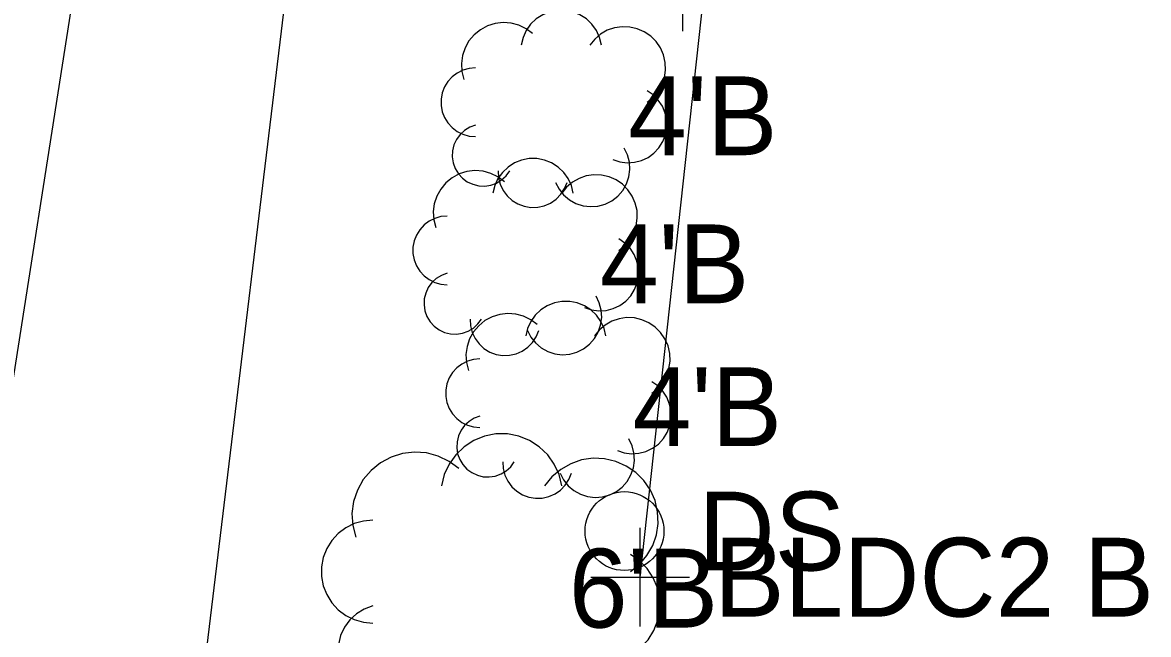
# Model space of a CAD drawing. Extents: x 1363693 to 1365209, y 422201 to 424153.
# Drawn here: x 1364320.23 to 1364343.06, y 423350.74 to 423363.16 of the extents above; entities that cross this region are included whole.
import ezdxf

# ---------------------------------------------------------------- set-up
doc = ezdxf.new("R2010")
doc.units = 0
for name, color, linetype in [('BD_X_Building', 7, 'Continuous'), ('DR_X_Cells', 7, 'Continuous'), ('DR_X_Text', 7, 'Continuous'), ('PV_X_Driveway', 7, 'Continuous'), ('SV_X_Original_Ground', 7, 'Continuous'), ('SV_X_Shot_Marker', 7, 'Continuous'), ('VG_X_Cells', 7, 'Continuous'), ('VG_X_Text', 7, 'Continuous')]:
    doc.layers.add(name, color=color, linetype=linetype)

msp = doc.modelspace()

# ---------------------------------------------------------------- linework, layer by layer
at = {"layer": 'BD_X_Building'}
msp.add_line((1364332.753, 423351.902), (1364336.998, 423390.69), dxfattribs=at)
at = {"layer": 'DR_X_Cells'}
msp.add_circle((1364332.436, 423352.838), 0.8, dxfattribs=at)
at = {"layer": 'PV_X_Driveway'}
for points in [[(1364331.792, 423345.218), (1364318.569, 423346.527), (1364322.532, 423371.799)], [(1364332.146, 423348.047), (1364323.796, 423349.002), (1364325.909, 423366.51), (1364326.847, 423366.42)]]:
    msp.add_lwpolyline(points, dxfattribs=at)
at = {"layer": 'SV_X_Original_Ground'}
msp.add_line((1364333.622, 423362.98), (1364333.622, 423364.98), dxfattribs=at)
at = {"layer": 'SV_X_Shot_Marker'}
for p, q in [((1364332.753, 423350.902), (1364332.753, 423352.902)), ((1364331.753, 423351.902), (1364333.753, 423351.902))]:
    msp.add_line(p, q, dxfattribs=at)
at = {"layer": 'VG_X_Cells'}
for points in [[(1364331.968, 423362.699), (1364331.931, 423362.851), (1364331.866, 423362.993), (1364331.776, 423363.12), (1364331.663, 423363.228), (1364331.531, 423363.313), (1364331.386, 423363.371), (1364331.233, 423363.4), (1364331.077, 423363.4), (1364330.923, 423363.371), (1364330.779, 423363.313), (1364330.647, 423363.228), (1364330.534, 423363.12), (1364330.444, 423362.993), (1364330.379, 423362.851), (1364330.342, 423362.699)], [(1364330.574, 423362.931), (1364330.444, 423363.029), (1364330.297, 423363.101), (1364330.14, 423363.143), (1364329.977, 423363.156), (1364329.815, 423363.137), (1364329.659, 423363.088), (1364329.515, 423363.011), (1364329.389, 423362.908), (1364329.284, 423362.783), (1364329.204, 423362.64), (1364329.153, 423362.485), (1364329.131, 423362.324), (1364329.141, 423362.161), (1364329.181, 423362.002)], [(1364332.897, 423361.538), (1364333.017, 423361.636), (1364333.118, 423361.755), (1364333.195, 423361.89), (1364333.246, 423362.037), (1364333.268, 423362.191), (1364333.262, 423362.346), (1364333.227, 423362.498), (1364333.164, 423362.641), (1364333.077, 423362.769), (1364332.967, 423362.879), (1364332.838, 423362.967), (1364332.696, 423363.029), (1364332.544, 423363.064), (1364332.388, 423363.071), (1364332.234, 423363.048), (1364332.087, 423362.998), (1364331.952, 423362.921), (1364331.833, 423362.82), (1364331.735, 423362.699)], [(1364329.413, 423362.235), (1364329.285, 423362.223), (1364329.162, 423362.188), (1364329.047, 423362.13), (1364328.944, 423362.053), (1364328.857, 423361.958), (1364328.79, 423361.849), (1364328.743, 423361.729), (1364328.72, 423361.602), (1364328.72, 423361.474), (1364328.743, 423361.347), (1364328.79, 423361.227), (1364328.857, 423361.118), (1364328.944, 423361.023), (1364329.047, 423360.946), (1364329.162, 423360.888), (1364329.285, 423360.853), (1364329.413, 423360.841)], [(1364332.2, 423360.377), (1364332.341, 423360.33), (1364332.488, 423360.311), (1364332.636, 423360.32), (1364332.779, 423360.357), (1364332.913, 423360.42), (1364333.033, 423360.507), (1364333.134, 423360.616), (1364333.212, 423360.741), (1364333.266, 423360.88), (1364333.292, 423361.026), (1364333.29, 423361.174), (1364333.26, 423361.319), (1364333.204, 423361.456), (1364333.122, 423361.58), (1364333.018, 423361.686), (1364332.897, 423361.77)], [(1364329.413, 423361.074), (1364329.298, 423361.031), (1364329.193, 423360.967), (1364329.102, 423360.884), (1364329.03, 423360.785), (1364328.978, 423360.673), (1364328.949, 423360.554), (1364328.944, 423360.431), (1364328.962, 423360.31), (1364329.004, 423360.194), (1364329.068, 423360.089), (1364329.151, 423359.998), (1364329.25, 423359.926), (1364329.362, 423359.874), (1364329.481, 423359.844), (1364329.604, 423359.839), (1364329.725, 423359.857), (1364329.841, 423359.899), (1364329.946, 423359.963), (1364330.037, 423360.046), (1364330.11, 423360.145)], [(1364331.039, 423359.913), (1364331.109, 423359.778), (1364331.203, 423359.659), (1364331.319, 423359.561), (1364331.452, 423359.487), (1364331.596, 423359.44), (1364331.747, 423359.421), (1364331.898, 423359.433), (1364332.044, 423359.473), (1364332.18, 423359.541), (1364332.3, 423359.634), (1364332.4, 423359.748), (1364332.476, 423359.88), (1364332.525, 423360.023), (1364332.546, 423360.174), (1364332.536, 423360.325), (1364332.498, 423360.472), (1364332.432, 423360.609)], [(1364331.396, 423359.694), (1364331.359, 423359.846), (1364331.294, 423359.988), (1364331.204, 423360.115), (1364331.091, 423360.223), (1364330.959, 423360.308), (1364330.814, 423360.366), (1364330.661, 423360.395), (1364330.505, 423360.395), (1364330.351, 423360.366), (1364330.207, 423360.308), (1364330.075, 423360.223), (1364329.962, 423360.115), (1364329.872, 423359.988), (1364329.807, 423359.846), (1364329.77, 423359.694)], [(1364330.002, 423359.926), (1364329.872, 423360.024), (1364329.725, 423360.096), (1364329.568, 423360.138), (1364329.405, 423360.151), (1364329.243, 423360.132), (1364329.087, 423360.083), (1364328.943, 423360.006), (1364328.817, 423359.903), (1364328.712, 423359.778), (1364328.632, 423359.635), (1364328.581, 423359.48), (1364328.559, 423359.319), (1364328.569, 423359.156), (1364328.609, 423358.997)], [(1364329.878, 423360.145), (1364329.885, 423360.008), (1364329.919, 423359.875), (1364329.978, 423359.751), (1364330.059, 423359.641), (1364330.16, 423359.548), (1364330.276, 423359.476), (1364330.405, 423359.428), (1364330.54, 423359.406), (1364330.677, 423359.409), (1364330.811, 423359.439), (1364330.936, 423359.494), (1364331.049, 423359.573), (1364331.144, 423359.671), (1364331.219, 423359.786), (1364331.271, 423359.913)], [(1364332.325, 423358.533), (1364332.445, 423358.631), (1364332.546, 423358.75), (1364332.623, 423358.885), (1364332.674, 423359.032), (1364332.696, 423359.186), (1364332.69, 423359.341), (1364332.655, 423359.493), (1364332.592, 423359.636), (1364332.505, 423359.764), (1364332.395, 423359.874), (1364332.266, 423359.962), (1364332.124, 423360.024), (1364331.972, 423360.059), (1364331.816, 423360.066), (1364331.662, 423360.043), (1364331.515, 423359.993), (1364331.38, 423359.916), (1364331.261, 423359.815), (1364331.163, 423359.694)], [(1364328.841, 423359.23), (1364328.713, 423359.218), (1364328.59, 423359.183), (1364328.475, 423359.125), (1364328.372, 423359.048), (1364328.285, 423358.953), (1364328.218, 423358.844), (1364328.171, 423358.724), (1364328.148, 423358.597), (1364328.148, 423358.469), (1364328.171, 423358.342), (1364328.218, 423358.222), (1364328.285, 423358.113), (1364328.372, 423358.018), (1364328.475, 423357.941), (1364328.59, 423357.883), (1364328.713, 423357.848), (1364328.841, 423357.836)], [(1364331.628, 423357.372), (1364331.769, 423357.325), (1364331.916, 423357.306), (1364332.064, 423357.315), (1364332.207, 423357.352), (1364332.341, 423357.415), (1364332.461, 423357.502), (1364332.562, 423357.611), (1364332.64, 423357.736), (1364332.694, 423357.875), (1364332.72, 423358.021), (1364332.718, 423358.169), (1364332.688, 423358.314), (1364332.632, 423358.451), (1364332.55, 423358.575), (1364332.446, 423358.681), (1364332.325, 423358.765)], [(1364328.841, 423358.069), (1364328.726, 423358.026), (1364328.621, 423357.962), (1364328.53, 423357.879), (1364328.458, 423357.78), (1364328.406, 423357.668), (1364328.377, 423357.549), (1364328.372, 423357.426), (1364328.39, 423357.305), (1364328.432, 423357.189), (1364328.496, 423357.084), (1364328.579, 423356.993), (1364328.678, 423356.921), (1364328.79, 423356.869), (1364328.909, 423356.839), (1364329.032, 423356.834), (1364329.153, 423356.852), (1364329.269, 423356.894), (1364329.374, 423356.958), (1364329.465, 423357.041), (1364329.538, 423357.14)], [(1364332.06, 423356.796), (1364332.023, 423356.948), (1364331.958, 423357.09), (1364331.868, 423357.217), (1364331.755, 423357.325), (1364331.623, 423357.41), (1364331.478, 423357.468), (1364331.325, 423357.497), (1364331.169, 423357.497), (1364331.015, 423357.468), (1364330.871, 423357.41), (1364330.739, 423357.325), (1364330.626, 423357.217), (1364330.536, 423357.09), (1364330.471, 423356.948), (1364330.434, 423356.796)], [(1364330.467, 423356.908), (1364330.537, 423356.773), (1364330.631, 423356.654), (1364330.747, 423356.556), (1364330.88, 423356.482), (1364331.024, 423356.435), (1364331.175, 423356.416), (1364331.326, 423356.428), (1364331.472, 423356.468), (1364331.608, 423356.536), (1364331.728, 423356.629), (1364331.828, 423356.743), (1364331.904, 423356.875), (1364331.953, 423357.018), (1364331.974, 423357.169), (1364331.964, 423357.32), (1364331.926, 423357.467), (1364331.86, 423357.604)], [(1364330.666, 423357.028), (1364330.536, 423357.126), (1364330.389, 423357.198), (1364330.232, 423357.24), (1364330.069, 423357.253), (1364329.907, 423357.234), (1364329.751, 423357.185), (1364329.607, 423357.108), (1364329.481, 423357.005), (1364329.376, 423356.88), (1364329.296, 423356.737), (1364329.245, 423356.582), (1364329.223, 423356.421), (1364329.233, 423356.258), (1364329.273, 423356.099)], [(1364329.306, 423357.14), (1364329.313, 423357.003), (1364329.347, 423356.87), (1364329.406, 423356.746), (1364329.487, 423356.636), (1364329.588, 423356.543), (1364329.704, 423356.471), (1364329.833, 423356.423), (1364329.968, 423356.401), (1364330.105, 423356.404), (1364330.239, 423356.434), (1364330.364, 423356.489), (1364330.477, 423356.568), (1364330.572, 423356.666), (1364330.647, 423356.781), (1364330.699, 423356.908)], [(1364332.989, 423355.635), (1364333.109, 423355.733), (1364333.21, 423355.852), (1364333.287, 423355.987), (1364333.338, 423356.134), (1364333.36, 423356.288), (1364333.354, 423356.443), (1364333.319, 423356.595), (1364333.256, 423356.738), (1364333.169, 423356.866), (1364333.059, 423356.976), (1364332.93, 423357.064), (1364332.788, 423357.126), (1364332.636, 423357.161), (1364332.48, 423357.168), (1364332.326, 423357.145), (1364332.179, 423357.095), (1364332.044, 423357.018), (1364331.925, 423356.917), (1364331.827, 423356.796)], [(1364329.505, 423356.332), (1364329.377, 423356.32), (1364329.254, 423356.285), (1364329.139, 423356.227), (1364329.036, 423356.15), (1364328.949, 423356.055), (1364328.882, 423355.946), (1364328.835, 423355.826), (1364328.812, 423355.699), (1364328.812, 423355.571), (1364328.835, 423355.444), (1364328.882, 423355.324), (1364328.949, 423355.215), (1364329.036, 423355.12), (1364329.139, 423355.043), (1364329.254, 423354.985), (1364329.377, 423354.95), (1364329.505, 423354.938)], [(1364332.292, 423354.474), (1364332.433, 423354.427), (1364332.58, 423354.408), (1364332.728, 423354.417), (1364332.871, 423354.454), (1364333.005, 423354.517), (1364333.125, 423354.604), (1364333.226, 423354.713), (1364333.304, 423354.838), (1364333.358, 423354.977), (1364333.384, 423355.123), (1364333.382, 423355.271), (1364333.352, 423355.416), (1364333.296, 423355.553), (1364333.214, 423355.677), (1364333.11, 423355.783), (1364332.989, 423355.867)], [(1364329.505, 423355.171), (1364329.39, 423355.128), (1364329.285, 423355.064), (1364329.194, 423354.981), (1364329.122, 423354.882), (1364329.07, 423354.77), (1364329.041, 423354.651), (1364329.036, 423354.528), (1364329.054, 423354.407), (1364329.096, 423354.291), (1364329.16, 423354.186), (1364329.243, 423354.095), (1364329.342, 423354.023), (1364329.454, 423353.971), (1364329.573, 423353.941), (1364329.696, 423353.936), (1364329.817, 423353.954), (1364329.933, 423353.996), (1364330.038, 423354.06), (1364330.129, 423354.143), (1364330.202, 423354.242)], [(1364331.167, 423353.757), (1364331.111, 423353.984), (1364331.014, 423354.197), (1364330.879, 423354.388), (1364330.709, 423354.55), (1364330.512, 423354.677), (1364330.295, 423354.764), (1364330.065, 423354.808), (1364329.83, 423354.808), (1364329.6, 423354.764), (1364329.383, 423354.677), (1364329.186, 423354.55), (1364329.016, 423354.388), (1364328.88, 423354.197), (1364328.783, 423353.984), (1364328.728, 423353.757)], [(1364331.131, 423354.01), (1364331.201, 423353.875), (1364331.295, 423353.756), (1364331.411, 423353.658), (1364331.544, 423353.584), (1364331.688, 423353.537), (1364331.839, 423353.518), (1364331.99, 423353.53), (1364332.136, 423353.57), (1364332.272, 423353.638), (1364332.392, 423353.731), (1364332.492, 423353.845), (1364332.568, 423353.977), (1364332.617, 423354.12), (1364332.638, 423354.271), (1364332.628, 423354.422), (1364332.59, 423354.569), (1364332.524, 423354.706)], [(1364329.077, 423354.105), (1364328.881, 423354.252), (1364328.661, 423354.359), (1364328.424, 423354.423), (1364328.18, 423354.441), (1364327.937, 423354.413), (1364327.703, 423354.34), (1364327.488, 423354.224), (1364327.298, 423354.07), (1364327.14, 423353.882), (1364327.021, 423353.669), (1364326.944, 423353.436), (1364326.912, 423353.193), (1364326.927, 423352.949), (1364326.987, 423352.712)], [(1364332.56, 423352.015), (1364332.741, 423352.162), (1364332.892, 423352.34), (1364333.008, 423352.543), (1364333.084, 423352.764), (1364333.117, 423352.994), (1364333.108, 423353.228), (1364333.055, 423353.455), (1364332.962, 423353.669), (1364332.83, 423353.862), (1364332.665, 423354.027), (1364332.472, 423354.158), (1364332.258, 423354.252), (1364332.031, 423354.305), (1364331.798, 423354.314), (1364331.567, 423354.28), (1364331.346, 423354.204), (1364331.143, 423354.089), (1364330.965, 423353.938), (1364330.818, 423353.757)], [(1364329.97, 423354.242), (1364329.977, 423354.105), (1364330.011, 423353.972), (1364330.07, 423353.848), (1364330.151, 423353.738), (1364330.252, 423353.645), (1364330.368, 423353.573), (1364330.497, 423353.525), (1364330.632, 423353.503), (1364330.769, 423353.506), (1364330.903, 423353.536), (1364331.028, 423353.591), (1364331.141, 423353.67), (1364331.236, 423353.768), (1364331.311, 423353.883), (1364331.363, 423354.01)], [(1364327.335, 423353.06), (1364327.143, 423353.042), (1364326.958, 423352.989), (1364326.785, 423352.903), (1364326.631, 423352.787), (1364326.501, 423352.645), (1364326.4, 423352.481), (1364326.33, 423352.301), (1364326.295, 423352.111), (1364326.295, 423351.919), (1364326.33, 423351.729), (1364326.4, 423351.549), (1364326.501, 423351.385), (1364326.631, 423351.243), (1364326.785, 423351.127), (1364326.958, 423351.041), (1364327.143, 423350.988), (1364327.335, 423350.97)], [(1364331.515, 423350.273), (1364331.726, 423350.203), (1364331.946, 423350.174), (1364332.168, 423350.188), (1364332.384, 423350.243), (1364332.585, 423350.338), (1364332.764, 423350.469), (1364332.916, 423350.632), (1364333.034, 423350.82), (1364333.114, 423351.028), (1364333.153, 423351.246), (1364333.15, 423351.469), (1364333.106, 423351.687), (1364333.02, 423351.892), (1364332.898, 423352.078), (1364332.743, 423352.237), (1364332.56, 423352.363)], [(1364327.335, 423351.318), (1364327.162, 423351.255), (1364327.004, 423351.159), (1364326.869, 423351.034), (1364326.76, 423350.885), (1364326.682, 423350.718), (1364326.638, 423350.539), (1364326.63, 423350.355), (1364326.658, 423350.173), (1364326.722, 423349.999), (1364326.817, 423349.842), (1364326.942, 423349.706), (1364327.09, 423349.596), (1364327.258, 423349.518), (1364327.437, 423349.474), (1364327.621, 423349.466), (1364327.803, 423349.494), (1364327.977, 423349.557), (1364328.134, 423349.652), (1364328.271, 423349.777), (1364328.38, 423349.925)]]:
    msp.add_lwpolyline(points, dxfattribs=at)

# ---------------------------------------------------------------- texts
at = {"layer": 'DR_X_Text'}
msp.add_text('DS', height=1.6, dxfattribs=at).set_placement((1364333.936, 423352.038))
at = {"layer": 'SV_X_Shot_Marker'}
msp.add_text('BLDC2 B', height=1.6, dxfattribs=at).set_placement((1364334.253, 423351.102))
at = {"layer": 'VG_X_Text'}
for s, p in [("4'B", (1364332.511, 423360.464)), ("4'B", (1364331.939, 423357.459)), ("4'B", (1364332.603, 423354.561)), ("6'B", (1364331.309, 423350.88))]:
    msp.add_text(s, height=1.6, dxfattribs=at).set_placement(p)

doc.saveas('drawing.dxf')
